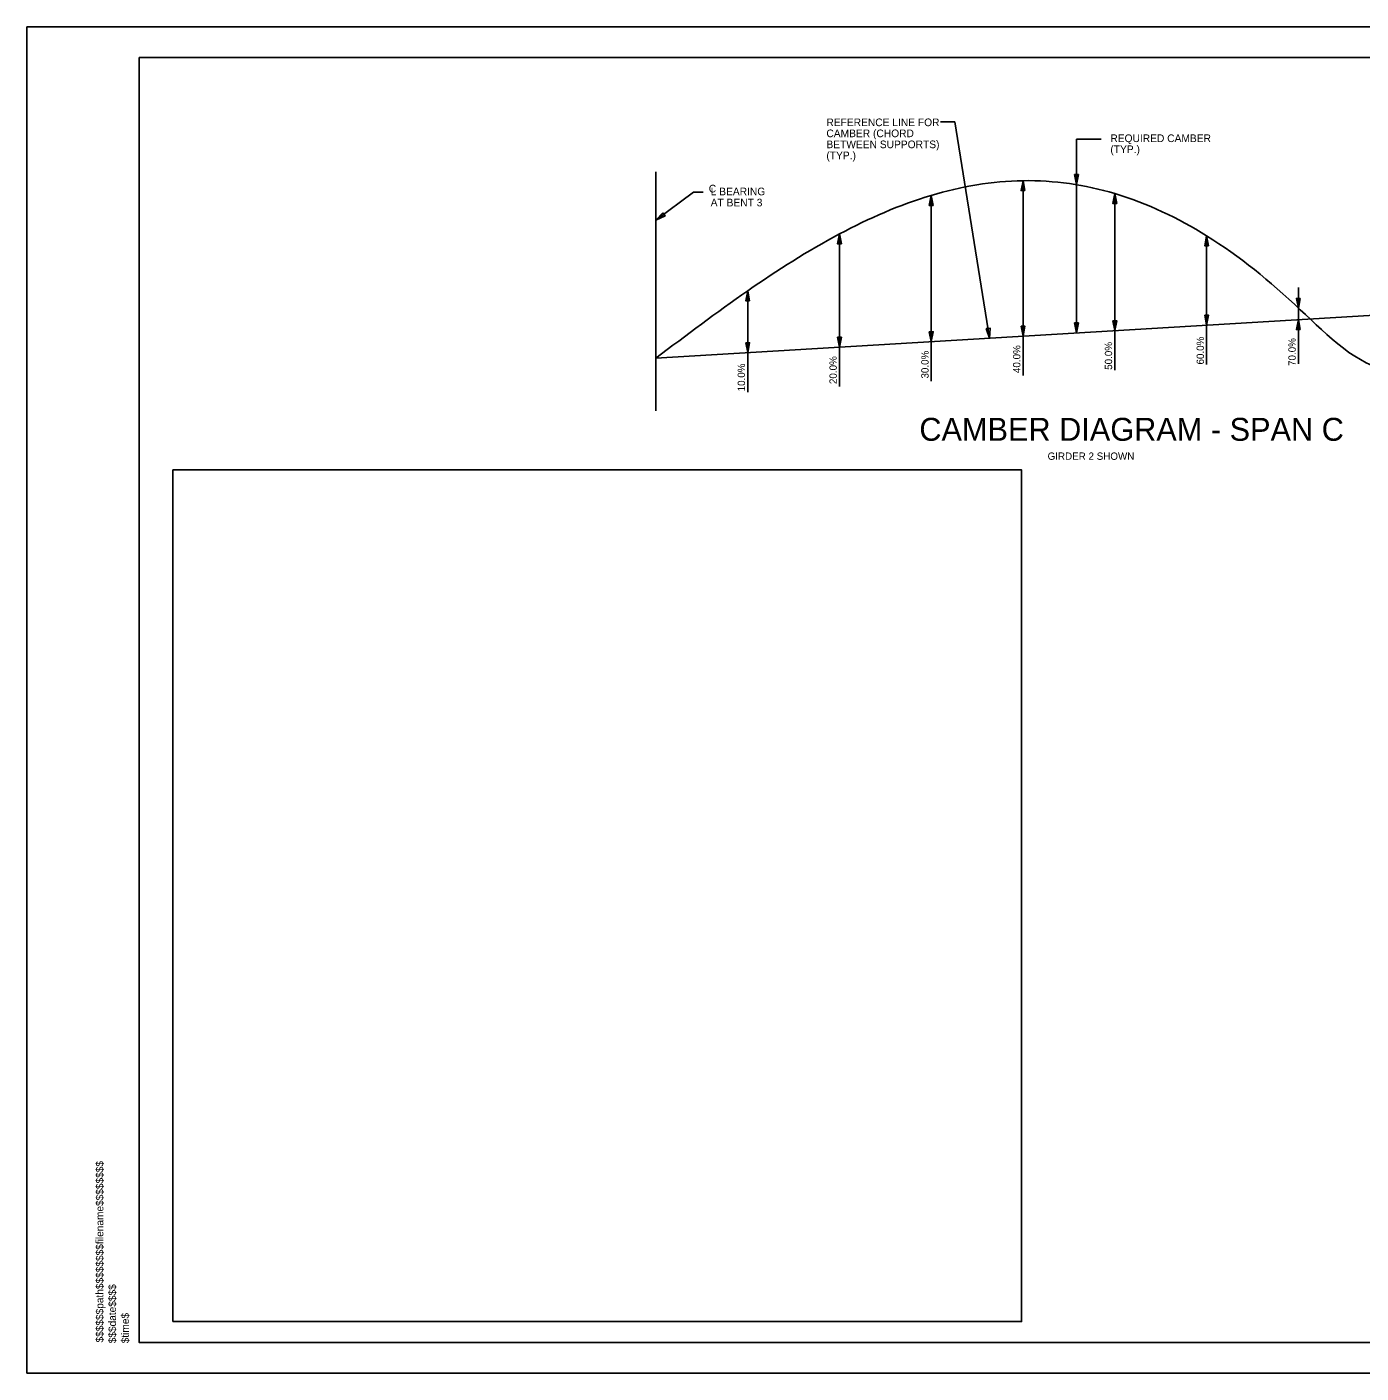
# Model space of a CAD drawing. Extents: x -125.5 to -89.4, y -5.1 to 16.9.
# Drawn here: x -125.53 to -103.73, y -5.07 to 16.93 of the extents above; entities that cross this region are included whole.
import ezdxf

# ---------------------------------------------------------------- set-up
doc = ezdxf.new("R2010")
doc.units = 0
for name, color, linetype in [('BR_AUTO DIMENSION', 7, 'Continuous'), ('BR_BORDER LINES', 7, 'Continuous'), ('BR_CENTER LINES', 7, 'Continuous'), ('BR_TABLE LINES', 7, 'Continuous'), ('BR_TEXT', 7, 'Continuous'), ('Level 31', 7, 'Continuous'), ('RD_SHT_ID', 7, 'Continuous')]:
    doc.layers.add(name, color=color, linetype=linetype)

msp = doc.modelspace()

# ---------------------------------------------------------------- linework, layer by layer
at = {"layer": 'BR_AUTO DIMENSION'}
for p, q in [((-110.6, 15.385), (-110.37, 15.385)), ((-110.37, 15.385), (-109.802, 11.848)), ((-108.379, 11.933), (-108.379, 15.097)), ((-108.379, 15.097), (-107.977, 15.097)), ((-114.641, 14.234), (-115.253, 13.776)), ((-114.481, 14.234), (-114.641, 14.234))]:
    msp.add_line(p, q, dxfattribs=at)
for points in [[(-108.41, 14.521), (-108.379, 14.359), (-108.347, 14.521)], [(-109.222, 14.258), (-109.253, 14.421), (-109.285, 14.258)], [(-110.722, 14.018), (-110.753, 14.181), (-110.785, 14.018)], [(-107.722, 14.048), (-107.753, 14.211), (-107.785, 14.048)], [(-115.141, 13.897), (-115.253, 13.776), (-115.104, 13.846)], [(-112.222, 13.388), (-112.253, 13.551), (-112.285, 13.388)], [(-106.222, 13.358), (-106.253, 13.521), (-106.285, 13.358)], [(-113.722, 12.458), (-113.753, 12.621), (-113.785, 12.458)], [(-104.722, 12.498), (-104.753, 12.335), (-104.785, 12.498)], [(-107.785, 12.133), (-107.753, 11.971), (-107.722, 12.133)], [(-106.285, 12.223), (-106.253, 12.061), (-106.222, 12.223)], [(-104.722, 11.988), (-104.753, 12.151), (-104.785, 11.988)], [(-110.785, 11.953), (-110.753, 11.791), (-110.722, 11.953)], [(-109.854, 12.005), (-109.802, 11.848), (-109.792, 12.013)], [(-109.285, 12.043), (-109.253, 11.881), (-109.222, 12.043)], [(-108.41, 12.096), (-108.379, 11.933), (-108.347, 12.096)], [(-113.785, 11.773), (-113.753, 11.611), (-113.722, 11.773)], [(-112.285, 11.863), (-112.253, 11.701), (-112.222, 11.863)]]:
    msp.add_lwpolyline(points, close=True, dxfattribs=at)
at = {"layer": 'BR_BORDER LINES'}
for p, q in [((-90.033, 16.434), (-123.699, 16.434)), ((-123.699, -4.566), (-123.699, 16.434)), ((-123.699, -4.566), (-90.033, -4.566))]:
    msp.add_line(p, q, dxfattribs=at)
at = {"layer": 'BR_CENTER LINES'}
msp.add_line((-115.253, 10.659), (-115.253, 14.566), dxfattribs=at)
at = {"layer": 'BR_TABLE LINES'}
for p, q in [((-109.253, 11.236), (-109.253, 14.421)), ((-110.753, 11.146), (-110.753, 14.181)), ((-107.753, 11.326), (-107.753, 14.211)), ((-112.253, 11.056), (-112.253, 13.551)), ((-106.253, 11.416), (-106.253, 13.521)), ((-113.753, 10.966), (-113.753, 12.621)), ((-104.753, 11.426), (-104.753, 12.673)), ((-100.257, 12.42), (-115.253, 11.521))]:
    msp.add_line(p, q, dxfattribs=at)
for points in [[(-123.699, 16.434), (-90.033, 16.434), (-90.033, -4.566), (-123.699, -4.566)], [(-123.148, -4.224), (-109.276, -4.224), (-109.276, 9.695), (-123.148, 9.695)]]:
    msp.add_lwpolyline(points, close=True, dxfattribs=at)
msp.add_spline([(-115.253, 11.521), (-113.753, 12.621), (-112.253, 13.551), (-110.753, 14.181), (-109.253, 14.421), (-107.753, 14.211), (-106.253, 13.521), (-104.724, 12.313), (-103.253, 11.324), (-101.692, 11.812), (-100.257, 12.42)], degree=3, dxfattribs=at)
at = {"layer": 'Level 31'}
msp.add_lwpolyline([(-125.533, -5.066), (-89.533, -5.066), (-89.533, 16.934), (-125.533, 16.934)], close=True, dxfattribs=at)

# ---------------------------------------------------------------- texts
at = {"layer": 'BR_AUTO DIMENSION'}
for s, p in [('REFERENCE LINE FOR', (-112.467, 15.312)), ('CAMBER (CHORD', (-112.467, 15.132)), ('BETWEEN SUPPORTS)', (-112.467, 14.952)), ('(TYP.)', (-107.826, 14.872)), ('REQUIRED CAMBER', (-107.826, 15.052)), ('(TYP.)', (-112.467, 14.771)), ('C', (-114.389, 14.229)), ('L BEARING', (-114.358, 14.182)), ('AT BENT 3', (-114.358, 14.001))]:
    msp.add_text(s, height=0.125, dxfattribs=at).set_placement(p)
at = {"layer": 'BR_TEXT'}
for s, p in [('40.0%', (-109.297, 11.277)), ('50.0%', (-107.797, 11.33)), ('60.0%', (-106.297, 11.417)), ('70.0%', (-104.797, 11.393)), ('20.0%', (-112.297, 11.097)), ('30.0%', (-110.797, 11.187)), ('10.0%', (-113.797, 10.978))]:
    msp.add_text(s, height=0.12, rotation=90, dxfattribs=at).set_placement(p)
for s, height, p in [('CAMBER DIAGRAM - SPAN C', 0.375, (-110.948, 10.17)), ('GIRDER 2 SHOWN', 0.12, (-108.852, 9.859))]:
    msp.add_text(s, height=height, dxfattribs=at).set_placement(p)
at = {"layer": 'RD_SHT_ID'}
for s, height, p in [('$$$$$$path$$$$$$$$filename$$$$$$$$', 0.12347, (-124.283, -4.566)), ('$$$date$$$$', 0.12347, (-124.077, -4.579)), ('$time$', 0.1235, (-123.866, -4.579))]:
    msp.add_text(s, height=height, rotation=90, dxfattribs=at).set_placement(p)

doc.saveas('drawing.dxf')
